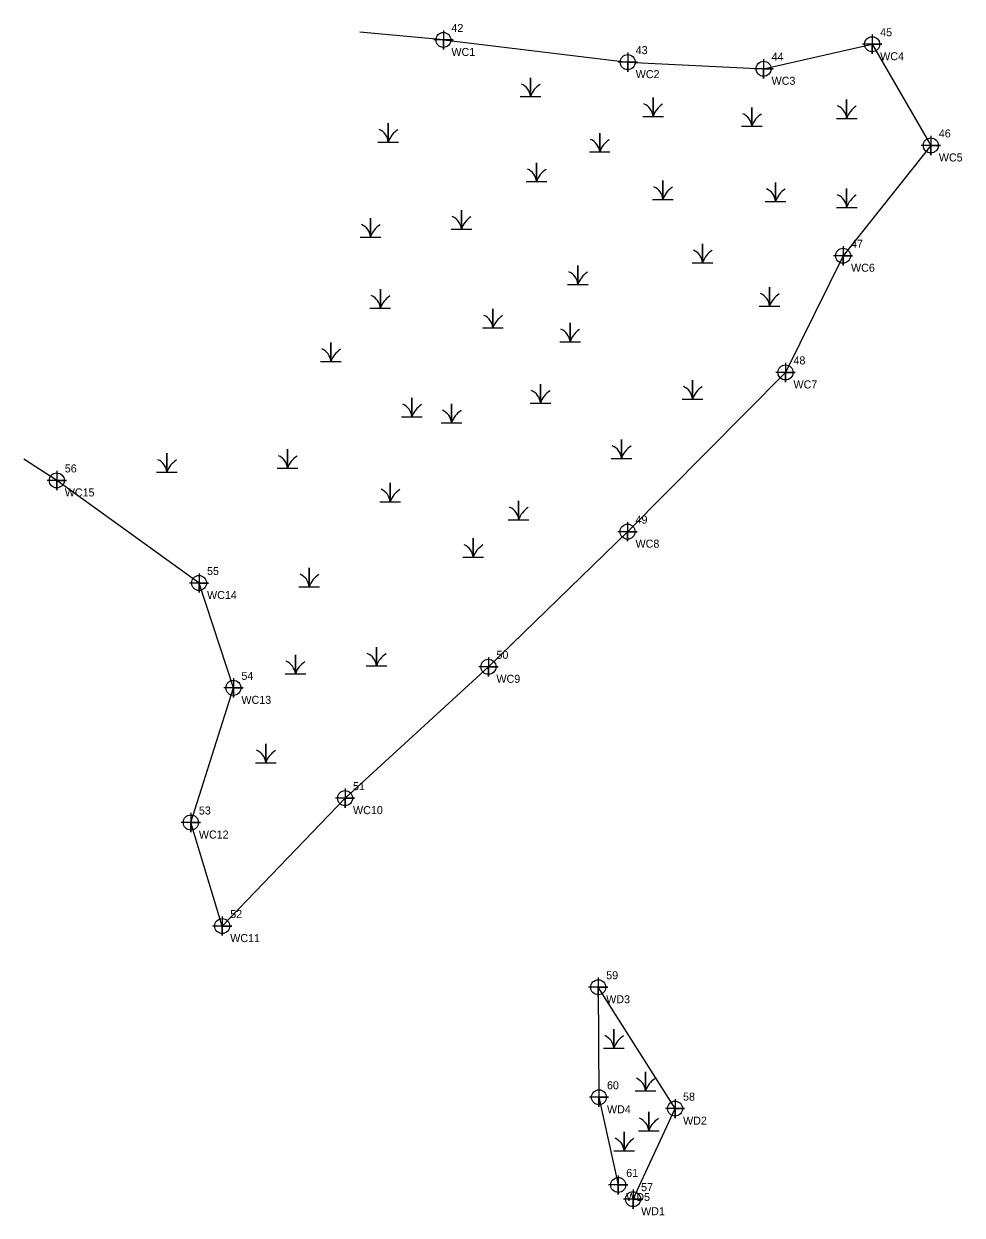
# Model space of a CAD drawing. Extents: x 2189822 to 2190837, y 387253 to 388663.
# Drawn here: x 2190544.1 to 2190837.1, y 388290.9 to 388662.9 of the extents above; entities that cross this region are included whole.
import ezdxf

# ---------------------------------------------------------------- set-up
doc = ezdxf.new("R2010")
doc.units = 0
for name, color, linetype in [('COGO Default Chain', 7, 'Continuous'), ('DTM Contours Major', 7, 'Continuous'), ('DTM Contours Minor', 7, 'Continuous'), ('Exist DTM Breakline Cogo Elevation', 7, 'Continuous'), ('Exist DTM Breakline Cogo Number', 7, 'Continuous')]:
    doc.layers.add(name, color=color, linetype=linetype)

msp = doc.modelspace()

# ---------------------------------------------------------------- linework, layer by layer
at = {"layer": 'DTM Contours Major'}
for points in [[(2190675.12, 388660.89), (2190675.12, 388654.89), (2190675.12, 388657.89), (2190678.12, 388657.89), (2190672.12, 388657.89)], [(2190808.98, 388659.55), (2190808.98, 388653.55), (2190808.98, 388656.55), (2190811.98, 388656.55), (2190805.98, 388656.55)], [(2190732.67, 388653.96), (2190732.67, 388647.96), (2190732.67, 388650.96), (2190735.67, 388650.96), (2190729.67, 388650.96)], [(2190775.08, 388651.89), (2190775.08, 388645.89), (2190775.08, 388648.89), (2190778.08, 388648.89), (2190772.08, 388648.89)], [(2190827.29, 388627.95), (2190827.29, 388621.95), (2190827.29, 388624.95), (2190830.29, 388624.95), (2190824.29, 388624.95)], [(2190799.88, 388593.51), (2190799.88, 388587.51), (2190799.88, 388590.51), (2190802.88, 388590.51), (2190796.88, 388590.51)], [(2190781.92, 388557.07), (2190781.92, 388551.07), (2190781.92, 388554.07), (2190784.92, 388554.07), (2190778.92, 388554.07)], [(2190554.41, 388523.35), (2190554.41, 388517.35), (2190554.41, 388520.35), (2190557.41, 388520.35), (2190551.41, 388520.35)], [(2190732.61, 388507.35), (2190732.61, 388501.35), (2190732.61, 388504.35), (2190735.61, 388504.35), (2190729.61, 388504.35)], [(2190598.83, 388491.32), (2190598.83, 388485.32), (2190598.83, 388488.32), (2190601.83, 388488.32), (2190595.83, 388488.32)], [(2190689.18, 388465.15), (2190689.18, 388459.15), (2190689.18, 388462.15), (2190692.18, 388462.15), (2190686.18, 388462.15)], [(2190609.56, 388458.58), (2190609.56, 388452.58), (2190609.56, 388455.58), (2190612.56, 388455.58), (2190606.56, 388455.58)], [(2190644.41, 388424.14), (2190644.41, 388418.14), (2190644.41, 388421.14), (2190647.41, 388421.14), (2190641.41, 388421.14)], [(2190596.27, 388416.53), (2190596.27, 388410.53), (2190596.27, 388413.53), (2190599.27, 388413.53), (2190593.27, 388413.53)], [(2190606.06, 388384.2), (2190606.06, 388378.2), (2190606.06, 388381.2), (2190609.06, 388381.2), (2190603.06, 388381.2)], [(2190723.45, 388365.09), (2190723.45, 388359.09), (2190723.45, 388362.09), (2190726.45, 388362.09), (2190720.45, 388362.09)], [(2190723.69, 388330.73), (2190723.69, 388324.73), (2190723.69, 388327.73), (2190726.69, 388327.73), (2190720.69, 388327.73)], [(2190747.44, 388327.19), (2190747.44, 388321.19), (2190747.44, 388324.19), (2190750.44, 388324.19), (2190744.44, 388324.19)], [(2190729.69, 388303.35), (2190729.69, 388297.35), (2190729.69, 388300.35), (2190732.69, 388300.35), (2190726.69, 388300.35)], [(2190734.34, 388298.92), (2190734.34, 388292.92), (2190734.34, 388295.92), (2190737.34, 388295.92), (2190731.34, 388295.92)]]:
    msp.add_lwpolyline(points, dxfattribs=at)
for centre in [(2190675.12, 388657.89), (2190808.98, 388656.55), (2190732.67, 388650.96), (2190775.08, 388648.89), (2190827.29, 388624.95), (2190799.88, 388590.51), (2190781.92, 388554.07), (2190554.41, 388520.35), (2190732.61, 388504.35), (2190598.83, 388488.32), (2190689.18, 388462.15), (2190609.56, 388455.58), (2190644.41, 388421.14), (2190596.27, 388413.53), (2190606.06, 388381.2), (2190723.45, 388362.09), (2190723.69, 388327.73), (2190747.44, 388324.19), (2190729.69, 388300.35), (2190734.34, 388295.92)]:
    msp.add_circle(centre, 2.34, dxfattribs=at)
at = {"layer": 'Exist DTM Breakline Cogo Elevation'}
for p, q in [((2190702.31, 388642.87), (2190702.31, 388642.87)), ((2190740.56, 388636.7), (2190740.56, 388636.7)), ((2190801.02, 388636.08), (2190801.02, 388636.08)), ((2190771.41, 388633.61), (2190771.41, 388633.61)), ((2190657.9, 388628.67), (2190657.9, 388628.67)), ((2190723.91, 388625.58), (2190723.91, 388625.58)), ((2190704.17, 388616.32), (2190704.17, 388616.32)), ((2190743.65, 388610.77), (2190743.65, 388610.77)), ((2190778.81, 388610.15), (2190778.81, 388610.15)), ((2190801.02, 388608.3), (2190801.02, 388608.3)), ((2190680.72, 388601.51), (2190680.72, 388601.51)), ((2190652.34, 388599.04), (2190652.34, 388599.04)), ((2190755.99, 388591.01), (2190755.99, 388591.01)), ((2190717.12, 388584.22), (2190717.12, 388584.22)), ((2190655.43, 388576.82), (2190655.43, 388576.82)), ((2190776.96, 388577.43), (2190776.96, 388577.43)), ((2190690.59, 388570.64), (2190690.59, 388570.64)), ((2190714.65, 388566.32), (2190714.65, 388566.32)), ((2190640.01, 388560.15), (2190640.01, 388560.15)), ((2190752.9, 388548.42), (2190752.9, 388548.42)), ((2190705.4, 388547.18), (2190705.4, 388547.18)), ((2190665.3, 388542.86), (2190665.3, 388542.86)), ((2190677.64, 388541.01), (2190677.64, 388541.01)), ((2190730.69, 388529.9), (2190730.69, 388529.9)), ((2190626.43, 388526.81), (2190626.43, 388526.81)), ((2190588.8, 388525.58), (2190588.8, 388525.58)), ((2190658.51, 388516.32), (2190658.51, 388516.32)), ((2190698.61, 388510.76), (2190698.61, 388510.76)), ((2190684.42, 388499.03), (2190684.42, 388499.03)), ((2190633.22, 388489.77), (2190633.22, 388489.77)), ((2190654.19, 388465.08), (2190654.19, 388465.08)), ((2190628.9, 388462.61), (2190628.9, 388462.61)), ((2190619.65, 388434.83), (2190619.65, 388434.83)), ((2190728.34, 388345.73), (2190728.34, 388345.73)), ((2190738.21, 388332.42), (2190738.21, 388332.42)), ((2190739.22, 388319.92), (2190739.22, 388319.92)), ((2190731.56, 388313.68), (2190731.56, 388313.68))]:
    msp.add_line(p, q, dxfattribs=at)
for points in [[(2190699.09, 388640.19), (2190702.32, 388640.19), (2190702.32, 388646.11), (2190702.32, 388640.19), (2190705.54, 388640.19)], [(2190737.34, 388634.02), (2190740.56, 388634.02), (2190740.56, 388639.94), (2190740.56, 388634.02), (2190743.79, 388634.02)], [(2190797.8, 388633.4), (2190801.02, 388633.4), (2190801.02, 388639.32), (2190801.02, 388633.4), (2190804.25, 388633.4)], [(2190768.18, 388630.93), (2190771.41, 388630.93), (2190771.41, 388636.85), (2190771.41, 388630.93), (2190774.64, 388630.93)], [(2190654.67, 388626), (2190657.9, 388626), (2190657.9, 388631.91), (2190657.9, 388626), (2190661.12, 388626)], [(2190720.68, 388622.91), (2190723.91, 388622.91), (2190723.91, 388628.83), (2190723.91, 388622.91), (2190727.13, 388622.91)], [(2190700.94, 388613.65), (2190704.17, 388613.65), (2190704.17, 388619.57), (2190704.17, 388613.65), (2190707.39, 388613.65)], [(2190740.42, 388608.09), (2190743.65, 388608.09), (2190743.65, 388614.01), (2190743.65, 388608.09), (2190746.87, 388608.09)], [(2190775.59, 388607.48), (2190778.81, 388607.48), (2190778.81, 388613.39), (2190778.81, 388607.48), (2190782.04, 388607.48)], [(2190797.8, 388605.62), (2190801.02, 388605.62), (2190801.02, 388611.54), (2190801.02, 388605.62), (2190804.25, 388605.62)], [(2190677.5, 388598.83), (2190680.72, 388598.83), (2190680.72, 388604.75), (2190680.72, 388598.83), (2190683.95, 388598.83)], [(2190649.12, 388596.36), (2190652.34, 388596.36), (2190652.34, 388602.28), (2190652.34, 388596.36), (2190655.57, 388596.36)], [(2190752.76, 388588.34), (2190755.99, 388588.34), (2190755.99, 388594.26), (2190755.99, 388588.34), (2190759.21, 388588.34)], [(2190713.9, 388581.55), (2190717.12, 388581.55), (2190717.12, 388587.47), (2190717.12, 388581.55), (2190720.35, 388581.55)], [(2190652.2, 388574.14), (2190655.43, 388574.14), (2190655.43, 388580.06), (2190655.43, 388574.14), (2190658.65, 388574.14)], [(2190773.74, 388574.76), (2190776.96, 388574.76), (2190776.96, 388580.68), (2190776.96, 388574.76), (2190780.19, 388574.76)], [(2190687.37, 388567.97), (2190690.59, 388567.97), (2190690.59, 388573.89), (2190690.59, 388567.97), (2190693.82, 388567.97)], [(2190711.43, 388563.65), (2190714.65, 388563.65), (2190714.65, 388569.56), (2190714.65, 388563.65), (2190717.88, 388563.65)], [(2190636.78, 388557.47), (2190640.01, 388557.47), (2190640.01, 388563.39), (2190640.01, 388557.47), (2190643.23, 388557.47)], [(2190702.17, 388544.51), (2190705.4, 388544.51), (2190705.4, 388550.43), (2190705.4, 388544.51), (2190708.63, 388544.51)], [(2190749.68, 388545.75), (2190752.9, 388545.75), (2190752.9, 388551.66), (2190752.9, 388545.75), (2190756.13, 388545.75)], [(2190662.07, 388540.19), (2190665.3, 388540.19), (2190665.3, 388546.11), (2190665.3, 388540.19), (2190668.53, 388540.19)], [(2190674.41, 388538.34), (2190677.64, 388538.34), (2190677.64, 388544.25), (2190677.64, 388538.34), (2190680.86, 388538.34)], [(2190623.21, 388524.14), (2190626.43, 388524.14), (2190626.43, 388530.06), (2190626.43, 388524.14), (2190629.66, 388524.14)], [(2190727.47, 388527.23), (2190730.69, 388527.23), (2190730.69, 388533.14), (2190730.69, 388527.23), (2190733.92, 388527.23)], [(2190585.58, 388522.9), (2190588.8, 388522.9), (2190588.8, 388528.82), (2190588.8, 388522.9), (2190592.03, 388522.9)], [(2190655.29, 388513.64), (2190658.51, 388513.64), (2190658.51, 388519.56), (2190658.51, 388513.64), (2190661.74, 388513.64)], [(2190695.39, 388508.09), (2190698.61, 388508.09), (2190698.61, 388514.01), (2190698.61, 388508.09), (2190701.84, 388508.09)], [(2190681.2, 388496.36), (2190684.42, 388496.36), (2190684.42, 388502.28), (2190684.42, 388496.36), (2190687.65, 388496.36)], [(2190629.99, 388487.1), (2190633.22, 388487.1), (2190633.22, 388493.02), (2190633.22, 388487.1), (2190636.45, 388487.1)], [(2190650.97, 388462.41), (2190654.2, 388462.41), (2190654.2, 388468.33), (2190654.2, 388462.41), (2190657.42, 388462.41)], [(2190625.68, 388459.94), (2190628.9, 388459.94), (2190628.9, 388465.86), (2190628.9, 388459.94), (2190632.13, 388459.94)], [(2190616.42, 388432.16), (2190619.65, 388432.16), (2190619.65, 388438.08), (2190619.65, 388432.16), (2190622.87, 388432.16)], [(2190725.11, 388343.05), (2190728.34, 388343.05), (2190728.34, 388348.97), (2190728.34, 388343.05), (2190731.56, 388343.05)], [(2190734.98, 388329.75), (2190738.21, 388329.75), (2190738.21, 388335.67), (2190738.21, 388329.75), (2190741.44, 388329.75)], [(2190735.99, 388317.25), (2190739.22, 388317.25), (2190739.22, 388323.17), (2190739.22, 388317.25), (2190742.44, 388317.25)], [(2190728.34, 388311), (2190731.56, 388311), (2190731.56, 388316.92), (2190731.56, 388311), (2190734.79, 388311)]]:
    msp.add_lwpolyline(points, dxfattribs=at)
for centre, radius, start, end in [((2190697.72, 388639.86), 4.61, 4.1403, 67.535), ((2190709.16, 388637.92), 7.21, 122.1274, 161.6222), ((2190735.96, 388633.69), 4.61, 4.1403, 67.535), ((2190747.4, 388631.75), 7.21, 122.1274, 161.6222), ((2190766.81, 388630.6), 4.61, 4.1403, 67.535), ((2190778.25, 388628.66), 7.21, 122.1274, 161.6222), ((2190796.42, 388633.07), 4.61, 4.1403, 67.535), ((2190807.86, 388631.13), 7.21, 122.1274, 161.6222), ((2190653.3, 388625.66), 4.61, 4.1403, 67.535), ((2190664.74, 388623.72), 7.21, 122.1274, 161.6222), ((2190719.31, 388622.58), 4.61, 4.1403, 67.535), ((2190730.75, 388620.64), 7.21, 122.1274, 161.6222), ((2190699.57, 388613.32), 4.61, 4.1403, 67.535), ((2190711.01, 388611.38), 7.21, 122.1274, 161.6222), ((2190739.05, 388607.76), 4.61, 4.1403, 67.535), ((2190750.49, 388605.82), 7.21, 122.1274, 161.6222), ((2190774.21, 388607.14), 4.61, 4.1403, 67.535), ((2190785.65, 388605.2), 7.21, 122.1274, 161.6222), ((2190796.42, 388605.29), 4.61, 4.1403, 67.535), ((2190807.86, 388603.35), 7.21, 122.1274, 161.6222), ((2190676.12, 388598.5), 4.61, 4.1403, 67.535), ((2190687.56, 388596.56), 7.21, 122.1274, 161.6222), ((2190647.74, 388596.03), 4.61, 4.1403, 67.535), ((2190659.19, 388594.09), 7.21, 122.1274, 161.6222), ((2190751.39, 388588.01), 4.61, 4.1403, 67.535), ((2190762.83, 388586.07), 7.21, 122.1274, 161.6222), ((2190712.52, 388581.22), 4.61, 4.1403, 67.535), ((2190723.96, 388579.28), 7.21, 122.1274, 161.6222), ((2190772.36, 388574.43), 4.61, 4.1403, 67.535), ((2190783.8, 388572.49), 7.21, 122.1274, 161.6222), ((2190650.83, 388573.81), 4.61, 4.1403, 67.535), ((2190662.27, 388571.87), 7.21, 122.1274, 161.6222), ((2190685.99, 388567.64), 4.61, 4.1403, 67.535), ((2190697.43, 388565.7), 7.21, 122.1274, 161.6222), ((2190710.05, 388563.31), 4.61, 4.1403, 67.535), ((2190721.49, 388561.37), 7.21, 122.1274, 161.6222), ((2190635.41, 388557.14), 4.61, 4.1403, 67.535), ((2190646.85, 388555.2), 7.21, 122.1274, 161.6222), ((2190700.8, 388544.18), 4.61, 4.1403, 67.535), ((2190712.24, 388542.24), 7.21, 122.1274, 161.6222), ((2190748.3, 388545.41), 4.61, 4.1403, 67.535), ((2190759.74, 388543.47), 7.21, 122.1274, 161.6222), ((2190660.7, 388539.86), 4.61, 4.1403, 67.535), ((2190672.14, 388537.92), 7.21, 122.1274, 161.6222), ((2190673.04, 388538), 4.61, 4.1403, 67.535), ((2190684.48, 388536.06), 7.21, 122.1274, 161.6222), ((2190726.09, 388526.89), 4.61, 4.1403, 67.535), ((2190737.53, 388524.95), 7.21, 122.1274, 161.6222), ((2190584.2, 388522.57), 4.61, 4.1403, 67.535), ((2190595.64, 388520.63), 7.21, 122.1274, 161.6222), ((2190621.83, 388523.81), 4.61, 4.1403, 67.535), ((2190633.27, 388521.87), 7.21, 122.1274, 161.6222), ((2190653.91, 388513.31), 4.61, 4.1403, 67.535), ((2190665.35, 388511.37), 7.21, 122.1274, 161.6222), ((2190694.01, 388507.76), 4.61, 4.1403, 67.535), ((2190705.45, 388505.82), 7.21, 122.1274, 161.6222), ((2190679.82, 388496.03), 4.61, 4.1403, 67.535), ((2190691.27, 388494.09), 7.21, 122.1274, 161.6222), ((2190628.62, 388486.77), 4.61, 4.1403, 67.535), ((2190640.06, 388484.83), 7.21, 122.1274, 161.6222), ((2190624.3, 388459.61), 4.61, 4.1403, 67.535), ((2190635.74, 388457.67), 7.21, 122.1274, 161.6222), ((2190649.6, 388462.07), 4.61, 4.1403, 67.535), ((2190661.04, 388460.13), 7.21, 122.1274, 161.6222), ((2190615.05, 388431.83), 4.61, 4.1403, 67.535), ((2190626.49, 388429.89), 7.21, 122.1274, 161.6222), ((2190723.74, 388342.72), 4.61, 4.1403, 67.535), ((2190735.18, 388340.78), 7.21, 122.1274, 161.6222), ((2190733.61, 388329.41), 4.61, 4.1403, 67.535), ((2190745.05, 388327.48), 7.21, 122.1274, 161.6222), ((2190734.62, 388316.92), 4.61, 4.1403, 67.535), ((2190746.06, 388314.98), 7.21, 122.1274, 161.6222), ((2190726.96, 388310.67), 4.61, 4.1403, 67.535), ((2190738.4, 388308.73), 7.21, 122.1274, 161.6222)]:
    msp.add_arc(centre, radius, start, end, dxfattribs=at)
at = {"layer": 'Exist DTM Breakline Cogo Number'}
for p, q in [((2190675.12, 388657.89), (2190648.98, 388660.35)), ((2190554.41, 388520.35), (2190544.13, 388526.98))]:
    msp.add_line(p, q, dxfattribs=at)
for points in [[(2190675.12, 388657.89), (2190732.67, 388650.96), (2190775.08, 388648.89), (2190808.98, 388656.55), (2190827.29, 388624.95), (2190799.88, 388590.51), (2190781.92, 388554.07), (2190732.61, 388504.35), (2190689.18, 388462.15), (2190644.41, 388421.14), (2190606.06, 388381.2), (2190596.27, 388413.53), (2190609.56, 388455.58), (2190598.83, 388488.32), (2190554.41, 388520.35)], [(2190734.34, 388295.92), (2190747.44, 388324.19), (2190723.45, 388362.09), (2190723.69, 388327.73), (2190729.69, 388300.35)]]:
    msp.add_lwpolyline(points, dxfattribs=at)

# ---------------------------------------------------------------- texts
at = {"layer": 'COGO Default Chain'}
for s, p in [('WC1', (2190677.62, 388652.89)), ('WC4', (2190811.48, 388651.55)), ('WC2', (2190735.17, 388645.96)), ('WC3', (2190777.58, 388643.89)), ('WC5', (2190829.79, 388619.95)), ('WC6', (2190802.38, 388585.51)), ('WC7', (2190784.42, 388549.07)), ('WC15', (2190556.91, 388515.35)), ('WC8', (2190735.11, 388499.35)), ('WC14', (2190601.33, 388483.32)), ('WC9', (2190691.68, 388457.15)), ('WC13', (2190612.06, 388450.58)), ('WC10', (2190646.91, 388416.14)), ('WC12', (2190598.77, 388408.53)), ('WC11', (2190608.56, 388376.2)), ('WD3', (2190725.95, 388357.09)), ('WD4', (2190726.19, 388322.73)), ('WD2', (2190749.94, 388319.19)), ('WD5', (2190732.19, 388295.35)), ('WD1', (2190736.84, 388290.92))]:
    msp.add_text(s, height=2.5, dxfattribs=at).set_placement(p)
at = {"layer": 'DTM Contours Minor'}
for s, p in [('42', (2190677.62, 388660.39)), ('45', (2190811.48, 388659.05)), ('43', (2190735.17, 388653.46)), ('44', (2190777.58, 388651.39)), ('46', (2190829.79, 388627.45)), ('47', (2190802.38, 388593.01)), ('48', (2190784.42, 388556.57)), ('56', (2190556.91, 388522.85)), ('49', (2190735.11, 388506.85)), ('55', (2190601.33, 388490.82)), ('50', (2190691.68, 388464.65)), ('54', (2190612.06, 388458.08)), ('51', (2190646.91, 388423.64)), ('53', (2190598.77, 388416.03)), ('52', (2190608.56, 388383.7)), ('59', (2190725.95, 388364.59)), ('60', (2190726.19, 388330.23)), ('58', (2190749.94, 388326.69)), ('61', (2190732.19, 388302.85)), ('57', (2190736.84, 388298.42))]:
    msp.add_text(s, height=2.5, dxfattribs=at).set_placement(p)

doc.saveas('drawing.dxf')
